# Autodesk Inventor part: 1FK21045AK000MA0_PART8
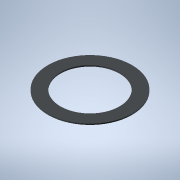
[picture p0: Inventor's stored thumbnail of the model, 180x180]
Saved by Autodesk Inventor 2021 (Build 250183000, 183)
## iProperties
Created: 2025-04
Part Number: 1FK21045AK000MA0_PART8
Material: Generic
Catalog Web Link: www.3dfindit.com
Description: -Servo synchronous motor
Document SubType Name: Modeling
Designer: psAdmin
Mass: 0.27214 g
Surface Area: 11.8752 cm^2
Volume: 0.27214 cm^3
Density: 1 g/cm^3
Appearance: PSOLRGB-212-217-219
Category: PARTsolutions
Title: 1FK21045AK000MA0_PART8
Author: Cadenas PARTsolutions
Comments: Servo synchronous motor
Sending System: PARTsolutions
Preprocessor: ST-DEVELOPER v19.3
PSOL_IDENT_0: {$CADENAS_DATA/23d-libs/siemens_ag/_cat_/3d/2f/1fk21045ak000ma0.prj},213 {VTYP=3D},{NB=1FK21045AK000
PSOL_IDENT_1: MA0_PART8},{LINA=1FK21045AK000MA0_PART8},{NN=1FK21045AK000MA0_PART8},{NOPRJ=TRUE},{DATE=19.08.2025 1
PSOL_IDENT_2: 4:00:34},{GEOMDATE=30.07.2025 02:01:24},{VERSION=},{LINEID=10},{WBVAR=},{WBNUMERIC=}  {NB=1FK21045AK
PSOL_IDENT_3: 000MA0_PART8},{LINA=1FK21045AK000MA0_PART8},{KT=DUMMY},{PREVIEW=../../../_pool_/a9/69/p_d211_xx_0081
PSOL_IDENT_4: 8j.png},{DESCSHORT=SIMOTICS S-1FK2 HD, SINAMICS S210 3AC 400V-480V, 1.7 Nm, 6000 rpm},{DESCLONG=SIMO
PSOL_IDENT_5: TICS S-1FK2 HD servo motor M0=2.4 Nm; PN = 1.07 kW at nN=6000 rpm (380-480 V); PN = 0.75 kW at nN=30
PSOL_IDENT_6: 00 rpm (200-240 V); degree of protection IP64; cylindrical shaft D19x40mm; absolute encoder 22-bit +
PSOL_IDENT_7: 12-bit multiturn (encoder AM22DQC); with OCC interface; plug size M17, rotatable; SIMOTICS S-1FK2 s
PSOL_IDENT_8: ervomotorfor a wide range of uses in industrial environments. SIMOTICS S‑1FK2 servomotors are compac
PSOL_IDENT_9: t synchronous motors with a high dynamic performance that set themselves apart as a result of their
PSOL_IDENT_10: high power density, degree of protection and overload capability. The motors are available in two va
PSOL_IDENT_11: riants: as High Dynamic variant (highest dynamic performance as a result of the low intrinsic moment
PSOL_IDENT_12: of inertia for applications demanding a high dynamic performance with low moved masses) - and as Co
PSOL_IDENT_13: mpact variant (precise and stable closed-loop control for medium up to large moved masses as a resul
PSOL_IDENT_14: t of a medium intrinsic moment of inertia). SIMOTICSS‑1FK2 servomotors fully exploit their strengths
PSOL_IDENT_15: in a system with the SINAMICSS210 frequency converter and simple connection using the one cable con
PSOL_IDENT_16: nection (OCC). Advantages include the short control and positioning times, fast and precise correcti
PSOL_IDENT_17: on of disturbing quantities as well as stable control with a high dynamic performance. The servo mot
PSOL_IDENT_18: ors can be configured to address a wide range of requirements. For example with and without holding
PSOL_IDENT_19: brake, IP64 or IP65 degree of protection, singleturn or multiturn absolute encoders - to name just a
PSOL_IDENT_20: few. Further, the servomotors are available in different shaft heights extending from 20 to 100. A
PSOL_IDENT_21: shaft sealing ring is available to achieve an IP65 degree of protection and for subsequent mounting
PSOL_IDENT_22: at the motor or as spare part. SIMOTICS - the optimum motor for each and every motion control applic
PSOL_IDENT_23: ation.},{INTNO=804766789342},{SUPPLIERALTNO=1FK2104-5AK00-0MA0},{MANUID=1FK21045AK000MA0},{MANUNAME=
PSOL_IDENT_24: Siemens},{MANUTYPEDESC=Synchronous motor 1FK2-HD 2,39 Nm},{AAU732=SIMOTICS},{AAO057=S-1FK2},{AAU734=
PSOL_IDENT_25: SIMOTICS S-1FK2 HD servo motor M0=2.4 Nm; PN = 1.07 kW at nN=6000 rpm (380-480 V); PN = 0.75 kW at n
PSOL_IDENT_26: N=3000 rpm (200-240 V); degree of protection IP64; cylindrical shaft D19x40mm; absolute encoder 22-b
PSOL_IDENT_27: it + 12-bit multiturn (encoder AM22DQC); with OCC interface; plug size M17, rotatable;},{AAW338=Sync
PSOL_IDENT_28: hronous motor 1FK2-HD 2,39 Nm},{AAO742=SIMOTICS},{AAO663=4042948691151},{NOCUPEROU=1},{PRICEQUANTITY=
PSOL_IDENT_29: 1},{QUANTITYMIN=1},{QUANTITYINT=1},{CTN=85015100},{COO=DE},{AAO676=1FK2104-5AK00-0MA0},{AAO677=Sieme
PSOL_IDENT_30: ns AG},{ORDERUNIT=C62},{CONTENTUNIT=C62}
NB: 1FK21045AK000MA0_PART8
NT: Servo synchronous motor
NBSYN: $MANUID._PART8
LINA: 1FK21045AK000MA0_PART8
CATALOG: SIEMENS
PREVIEW: ../../../_pool_/a9/69/p_d211_xx_00818j.png
DESCSHORT: SIMOTICS S-1FK2 HD, SINAMICS S210 3AC 400V-480V, 1.7 Nm, 6000 rpm
DESCLONG: SIMOTICS S-1FK2 HD servo motor M0=2.4 Nm; PN = 1.07 kW at nN=6000 rpm (380-480 V); PN = 0.75 kW at nN=3000 rpm (200-240 V); degree of protection IP64; cylindric
INTNO: 804766789342
SUPPLIERALTNO: 1FK2104-5AK00-0MA0
MANUID: 1FK21045AK000MA0
MANUNAME: Siemens
MANUTYPEDESC: Synchronous motor 1FK2-HD 2,39 Nm
AAU732: SIMOTICS
AAO057: S-1FK2
AAU734: SIMOTICS S-1FK2 HD servo motor M0=2.4 Nm; PN = 1.07 kW at nN=6000 rpm (380-480 V); PN = 0.75 kW at nN=3000 rpm (200-240 V); degree of protection IP64; cylindric
AAW338: Synchronous motor 1FK2-HD 2,39 Nm
AAO742: SIMOTICS
AAO663: 4042948691151.0
NOCUPEROU: 1
PRICEQUANTITY: 1
QUANTITYMIN: 1
QUANTITYINT: 1
CTN: 85015100
COO: DE
ARTICLENO: 1FK21045AK000MA0_PART8
BOMINFO: 1FK21045AK000MA0_PART8
CREATOR: CADENAS GmbH
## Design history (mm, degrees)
feature "2025_04_17_15_39_51_0728"
body "Solid1"
